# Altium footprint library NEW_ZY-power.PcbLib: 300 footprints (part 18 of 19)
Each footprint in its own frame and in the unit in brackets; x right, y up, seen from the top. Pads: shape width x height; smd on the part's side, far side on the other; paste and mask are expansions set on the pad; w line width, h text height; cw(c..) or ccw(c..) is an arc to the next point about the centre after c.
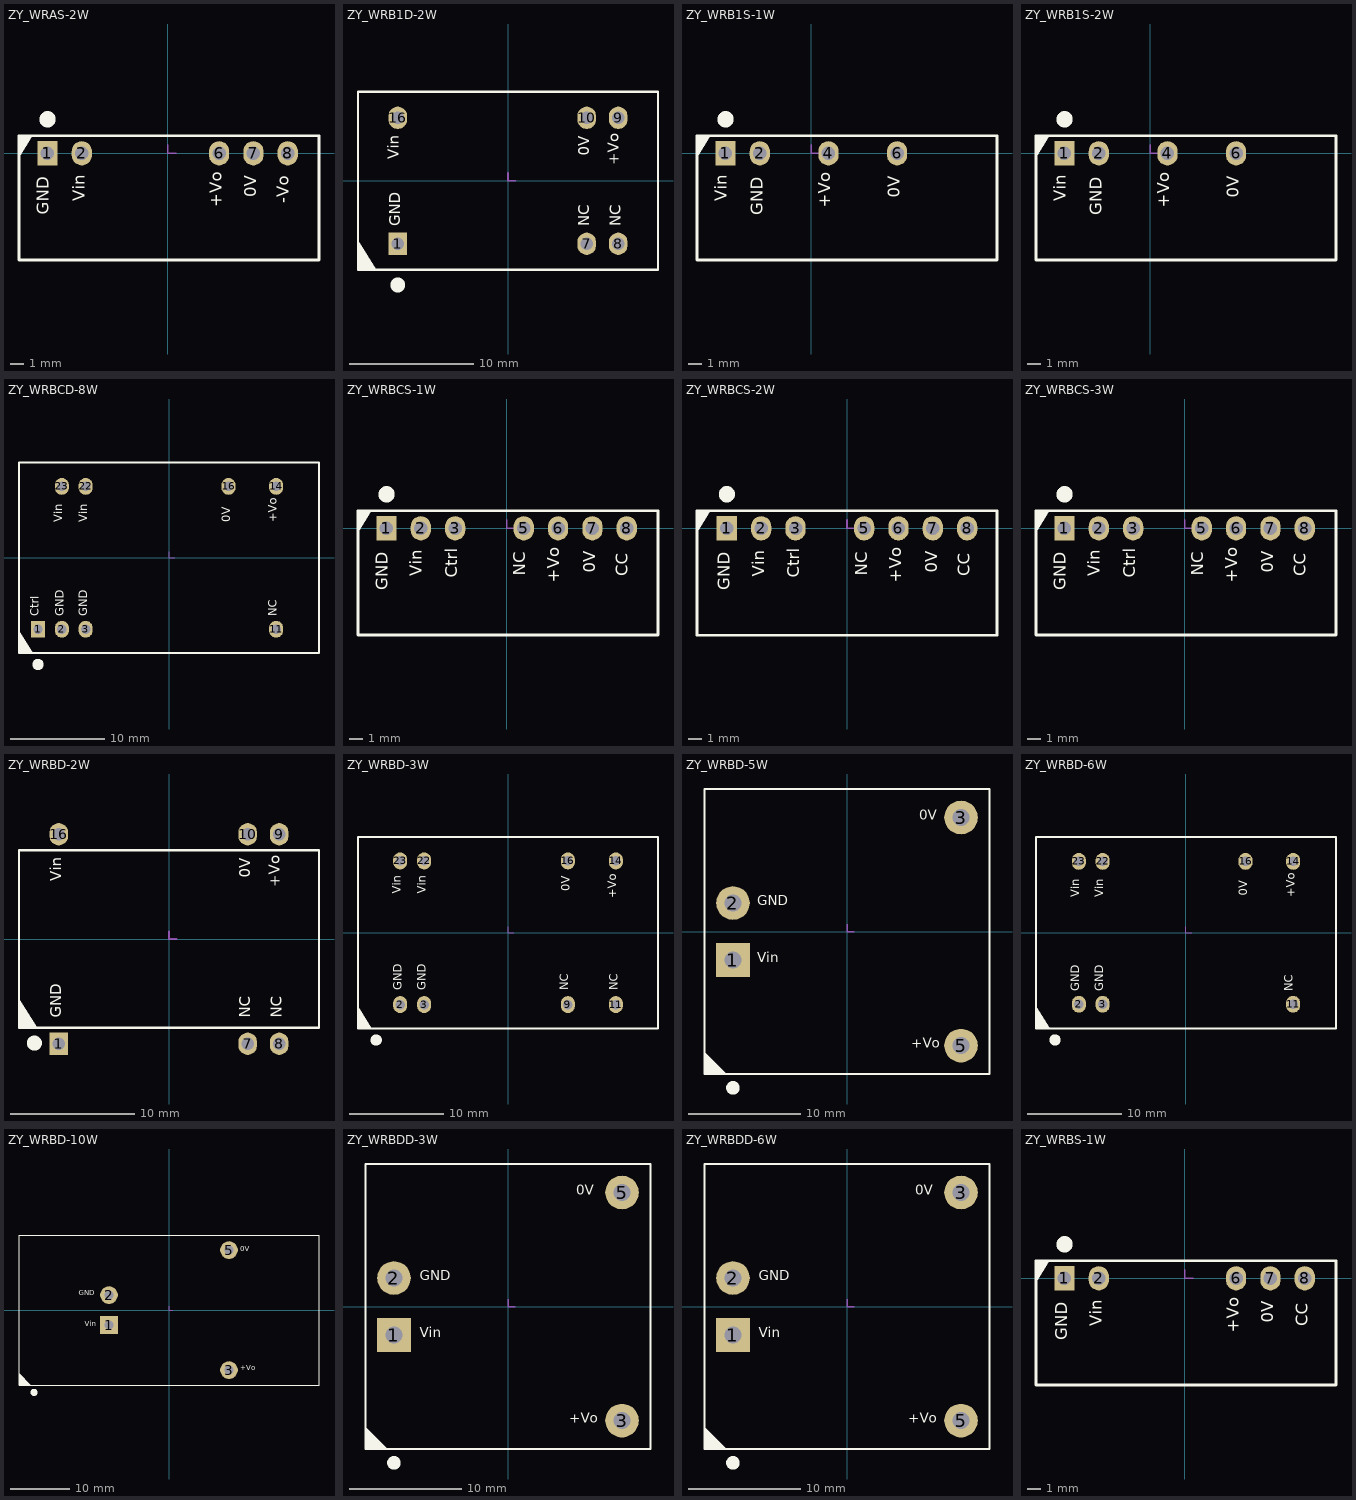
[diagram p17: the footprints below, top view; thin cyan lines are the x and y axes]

## ZY_WRAS-2W [mm]
height 12.2
pads (5):
  rect 1.5x1.8 hole 1: 1(-8.89,0)
  oval 1.5x1.8 hole 1: 2(-6.35,0) 6(3.81,0) 7(6.35,0) 8(8.89,0)
Top Overlay:
  circle w1: c-8.89,2.52 r0.1
  region: -10.998,-0.29 -10.998,1.295 -10.005,1.295
  lines w0.2: 11.201,-7.899 -10.998,-7.899 -10.998,1.295 11.201,1.295 11.201,-7.874
  text "GND" at -8.509,-4.547 h1.52
  text "Vin" at -5.842,-3.536 h1.52
  text "+Vo" at 4.318,-4.004 h1.52
  text "0V" at 6.858,-3.264 h1.52
  text "-Vo" at 9.271,-3.692 h1.52
Mechanical 15:
  lines w0.127: 0,0.635 0,0 0.635,0

## ZY_WRB1D-2W [mm]
height 8.3
pads (6):
  rect 1.5x1.8 hole 1: 1(-8.89,-5.08)
  oval 1.5x1.8 hole 1: 7(6.35,-5.08) 8(8.89,-5.08) 9(8.89,5.08) 10(6.35,5.08) 16(-8.89,5.08)
Top Overlay:
  circle w1: c-8.89,-8.4 r0.1
  region: -12.1,-4.845 -12.1,-7.175 -10.64,-7.175
  lines w0.2: -12.1,-7.175 -12.1,7.175 12.1,7.175 12.1,-7.175 -12.1,-7.175
  text "NC" at 6.858,-3.683 h1.52
  text "+Vo" at 9.271,1.27 h1.52
  text "0V" at 6.858,2.01 h1.52
  text "Vin" at -8.509,1.738 h1.52
  text "GND" at -8.382,-3.683 h1.52
  text "NC" at 9.398,-3.683 h1.52
Mechanical 15:
  lines w0.127: 0,0.635 0,0 0.635,0

## ZY_WRB1S-1W [mm]
height 12.2
pads (4):
  rect 1.5x1.8 hole 1: 1(-6.35,0)
  oval 1.5x1.8 hole 1: 2(-3.81,0) 4(1.27,0) 6(6.35,0)
Top Overlay:
  circle w1: c-6.35,2.52 r0.1
  region: -8.458,-0.29 -8.458,1.295 -7.465,1.295
  lines w0.2: 13.741,-7.899 -8.458,-7.899 -8.458,1.295 13.741,1.295 13.741,-7.874
  text "+Vo" at 1.702,-4.03 h1.52
  text "0V" at 6.858,-3.29 h1.52
  text "GND" at -3.302,-4.572 h1.52
  text "Vin" at -5.969,-3.562 h1.52
Mechanical 15:
  lines w0.127: 0,0.635 0,0 0.635,0

## ZY_WRB1S-2W [mm]
height 12.2
pads (4):
  rect 1.5x1.8 hole 1: 1(-6.35,0)
  oval 1.5x1.8 hole 1: 2(-3.81,0) 4(1.27,0) 6(6.35,0)
Top Overlay:
  circle w1: c-6.35,2.52 r0.1
  region: -8.458,-0.29 -8.458,1.295 -7.465,1.295
  lines w0.2: 13.741,-7.899 -8.458,-7.899 -8.458,1.295 13.741,1.295 13.741,-7.874
  text "Vin" at -5.969,-3.562 h1.52
  text "GND" at -3.302,-4.572 h1.52
  text "0V" at 6.858,-3.29 h1.52
  text "+Vo" at 1.702,-4.03 h1.52
Mechanical 15:
  lines w0.127: 0,0.635 0,0 0.635,0

## ZY_WRBCD-8W [mm]
pads (8):
  rect 1.5x1.8 hole 1: 1(-13.97,-7.62)
  oval 1.5x1.8 hole 1: 2(-11.43,-7.62) 3(-8.89,-7.62) 11(11.43,-7.62) 14(11.43,7.62) 16(6.35,7.62) 22(-8.89,7.62) 23(-11.43,7.62)
Top Overlay:
  circle w1: c-13.97,-11.375 r0.1
  region: -16,-7.82 -16,-10.15 -14.54,-10.15
  lines w0.2: -16,-10.15 16,-10.15 16,10.15 -16,10.15 -16,-10.15
  text "Ctrl" at -13.589,-6.223 h1.52
  text "Vin" at -11.049,3.81 h1.52
  text "Vin" at -8.382,3.81 h1.52
  text "0V" at 6.858,3.81 h1.52
  text "+Vo" at 11.811,3.81 h1.52
  text "NC" at 11.811,-6.223 h1.52
  text "GND" at -8.382,-6.223 h1.52
  text "GND" at -10.922,-6.223 h1.52
Mechanical 15:
  lines w0.127: 0,0.635 0,0 0.635,0

## ZY_WRBCS-1W [mm]
height 12.2
pads (7):
  rect 1.5x1.8 hole 1: 1(-8.89,0)
  oval 1.5x1.8 hole 1: 2(-6.35,0) 3(-3.81,0) 5(1.27,0) 6(3.81,0) 7(6.35,0) 8(8.89,0)
Top Overlay:
  circle w1: c-8.89,2.52 r0.1
  region: -10.998,-0.29 -10.998,1.295 -10.005,1.295
  lines w0.2: 11.201,-7.899 -10.998,-7.899 -10.998,1.295 11.201,1.295 11.201,-7.874
  text "CC" at 9.271,-3.536 h1.52
  text "0V" at 6.858,-3.29 h1.52
  text "+Vo" at 4.191,-4.03 h1.52
  text "Vin" at -5.969,-3.562 h1.52
  text "GND" at -8.509,-4.572 h1.52
  text "Ctrl" at -3.353,-3.646 h1.52
  text "NC" at 1.676,-3.501 h1.52
Mechanical 15:
  lines w0.127: 0,0.635 0,0 0.635,0

## ZY_WRBCS-2W [mm]
pads (7):
  rect 1.5x1.8 hole 1: 1(-8.89,0)
  oval 1.5x1.8 hole 1: 2(-6.35,0) 3(-3.81,0) 5(1.27,0) 6(3.81,0) 7(6.35,0) 8(8.89,0)
Top Overlay:
  circle w1: c-8.89,2.525 r0.1
  region: -11.1,-0.286 -11.1,1.3 -10.106,1.3
  lines w0.2: -11.1,-7.9 11.1,-7.9 11.1,1.3 -11.1,1.3 -11.1,-7.9
  text "CC" at 9.398,-3.538 h1.52
  text "0V" at 6.985,-3.291 h1.52
  text "+Vo" at 4.318,-4.031 h1.52
  text "Vin" at -5.842,-3.563 h1.52
  text "GND" at -8.382,-4.573 h1.52
  text "Ctrl" at -3.226,-3.648 h1.52
  text "NC" at 1.803,-3.502 h1.52
Mechanical 15:
  lines w0.127: 0,0.635 0,0 0.635,0

## ZY_WRBCS-3W [mm]
pads (7):
  rect 1.5x1.8 hole 1: 1(-8.89,0)
  oval 1.5x1.8 hole 1: 2(-6.35,0) 3(-3.81,0) 5(1.27,0) 6(3.81,0) 7(6.35,0) 8(8.89,0)
Top Overlay:
  circle w1: c-8.89,2.52 r0.1
  region: -10.998,-0.29 -10.998,1.295 -10.005,1.295
  lines w0.2: 11.201,-7.899 -10.998,-7.899 -10.998,1.295 11.201,1.295 11.201,-7.874
  text "GND" at -8.509,-4.572 h1.52
  text "Vin" at -5.969,-3.562 h1.52
  text "+Vo" at 4.191,-4.03 h1.52
  text "0V" at 6.858,-3.29 h1.52
  text "CC" at 9.271,-3.536 h1.52
  text "Ctrl" at -3.353,-3.646 h1.52
  text "NC" at 1.676,-3.501 h1.52
Mechanical 15:
  lines w0.127: 0,0.635 0,0 0.635,0

## ZY_WRBD-2W [mm]
pads (6):
  rect 1.5x1.8 hole 1: 1(-8.89,-8.45)
  oval 1.5x1.8 hole 1: 7(6.35,-8.45) 8(8.89,-8.45) 9(8.89,8.45) 10(6.35,8.45) 16(-8.89,8.45)
Top Overlay:
  circle w1: c-10.863,-8.4 r0.1
  region: -12.1,-4.845 -12.1,-7.175 -10.64,-7.175
  lines w0.2: -12.1,-7.175 12.1,-7.175 12.1,7.175 -12.1,7.175 -12.1,-7.175
  text "0V" at 6.858,4.931 h1.52
  text "+Vo" at 9.271,4.191 h1.52
  text "NC" at 9.398,-6.342 h1.52
  text "NC" at 6.858,-6.342 h1.52
  text "Vin" at -8.382,4.659 h1.52
  text "GND" at -8.382,-6.342 h1.52
Mechanical 15:
  lines w0.127: 0,0.635 0,0 0.635,0

## ZY_WRBD-3W [mm] "宽压输入隔离稳压单输出电源模块"
height 9.5
pads (8):
  oval 1.5x1.8 hole 1: 2(-11.43,-7.62) 3(-8.89,-7.62) 9(6.35,-7.62) 11(11.43,-7.62) 14(11.43,7.62) 16(6.35,7.62) 22(-8.89,7.62) 23(-11.43,7.62)
Top Overlay:
  circle w1: c-13.97,-11.375 r0.1
  region: -15.9,-7.82 -15.9,-10.15 -14.44,-10.15
  lines w0.2: -15.9,-10.15 -15.9,10.15 15.9,10.15 15.9,-10.15 -15.9,-10.15
  text "GND" at -10.922,-6.096 h1.52
  text "GND" at -8.382,-6.096 h1.52
  text "NC" at 6.731,-6.096 h1.52
  text "NC" at 11.938,-6.096 h1.52
  text "+Vo" at 11.811,3.683 h1.52
  text "0V" at 6.858,4.423 h1.52
  text "Vin" at -8.382,4.151 h1.52
  text "Vin" at -11.049,4.151 h1.52
Mechanical 15:
  lines w0.127: 0,0.635 0,0 0.635,0

## ZY_WRBD-5W [mm]
height 11.7
pads (4):
  rect 3x3 hole 1.5: 1(-10.16,-2.54)
  round 3 hole 1.5: 2(-10.16,2.54) 3(10.16,10.16) 5(10.16,-10.16)
Top Overlay:
  circle w1: c-10.16,-13.925 r0.1
  region: -12.7,-12.7 -10.725,-12.7 -12.7,-10.725
  lines w0.2: -12.7,-12.7 -12.7,12.7 12.7,12.7 12.7,-12.7 -12.7,-12.7
  text "0V" at 6.455,9.652 h1.52
  text "+Vo" at 5.715,-10.668 h1.52
  text "Vin" at -8.001,-3.048 h1.52
  text "GND" at -8.001,2.032 h1.52
Mechanical 15:
  lines w0.127: 0,0.635 0,0 0.635,0

## ZY_WRBD-6W [mm]
height 10.5
pads (7):
  oval 1.5x1.8 hole 1: 2(-11.43,-7.62) 3(-8.89,-7.62) 11(11.43,-7.62) 14(11.43,7.62) 16(6.35,7.62) 22(-8.89,7.62) 23(-11.43,7.62)
Top Overlay:
  circle w1: c-13.97,-11.425 r0.1
  region: -16,-7.87 -16,-10.2 -14.54,-10.2
  lines w0.2: -16,-10.2 16,-10.2 16,10.2 -16,10.2 -16,-10.2
  text "0V" at 6.858,3.937 h1.52
  text "+Vo" at 11.938,3.81 h1.52
  text "NC" at 11.684,-6.223 h1.52
  text "Vin" at -8.509,3.81 h1.52
  text "Vin" at -11.049,3.81 h1.52
  text "GND" at -8.509,-6.223 h1.52
  text "GND" at -11.049,-6.223 h1.52
Mechanical 15:
  lines w0.127: 0,0.635 0,0 0.635,0

## ZY_WRBD-10W [mm]
pads (4):
  rect 3x3 hole 1.5: 1(-10.16,-2.54)
  round 3 hole 1.5: 2(-10.16,2.54) 3(10.16,-10.16) 5(10.16,10.16)
Top Overlay:
  circle w1: c-22.86,-13.925 r0.1
  region: -25.4,-12.7 -23.425,-12.7 -25.4,-10.725
  lines w0.2: -25.4,-12.7 25.4,-12.7 25.4,12.7 -25.4,12.7 -25.4,-12.7
  text "Vin" at -14.231,-3.048 h1.52
  text "GND" at -15.241,2.159 h1.52
  text "0V" at 12.065,9.652 h1.52
  text "+Vo" at 12.065,-10.541 h1.52
Mechanical 15:
  lines w0.127: 0,0.635 0,0 0.635,0

## ZY_WRBDD-3W [mm]
height 11.7
pads (4):
  rect 3x3 hole 1.5: 1(-10.16,-2.54)
  round 3 hole 1.5: 2(-10.16,2.54) 3(10.16,-10.16) 5(10.16,10.16)
Top Overlay:
  circle w1: c-10.16,-13.925 r0.1
  region: -12.7,-12.7 -10.725,-12.7 -12.7,-10.725
  lines w0.2: -12.7,-12.7 12.7,-12.7 12.7,12.7 -12.7,12.7 -12.7,-12.7
  text "0V" at 6.074,9.652 h1.52
  text "+Vo" at 5.461,-10.668 h1.52
  text "Vin" at -7.874,-3.048 h1.52
  text "GND" at -7.875,2.032 h1.52
Mechanical 15:
  lines w0.127: 0,0.635 0,0 0.635,0

## ZY_WRBDD-6W [mm]
height 11.7
pads (4):
  rect 3x3 hole 1.5: 1(-10.16,-2.54)
  round 3 hole 1.5: 2(-10.16,2.54) 3(10.16,10.16) 5(10.16,-10.16)
Top Overlay:
  circle w1: c-10.16,-13.925 r0.1
  region: -12.7,-12.7 -10.725,-12.7 -12.7,-10.725
  lines w0.2: -12.7,-12.7 12.7,-12.7 12.7,12.7 -12.7,12.7 -12.7,-12.7
  text "0V" at 6.096,9.652 h1.52
  text "Vin" at -7.874,-3.048 h1.52
  text "GND" at -7.874,2.032 h1.52
  text "+Vo" at 5.461,-10.668 h1.52
Mechanical 15:
  lines w0.127: 0,0.635 0,0 0.635,0

## ZY_WRBS-1W [mm]
pads (5):
  rect 1.5x1.8 hole 1: 1(-8.89,0)
  oval 1.5x1.8 hole 1: 2(-6.35,0) 6(3.81,0) 7(6.35,0) 8(8.89,0)
Top Overlay:
  circle w1: c-8.89,2.52 r0.1
  region: -10.998,-0.29 -10.998,1.295 -10.005,1.295
  lines w0.2: 11.201,-7.899 -10.998,-7.899 -10.998,1.295 11.201,1.295 11.201,-7.874
  text "GND" at -8.382,-4.572 h1.52
  text "Vin" at -5.842,-3.562 h1.52
  text "+Vo" at 4.318,-4.03 h1.52
  text "0V" at 6.858,-3.29 h1.52
  text "CC" at 9.398,-3.536 h1.52
Mechanical 15:
  lines w0.127: 0,0.635 0,0 0.635,0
